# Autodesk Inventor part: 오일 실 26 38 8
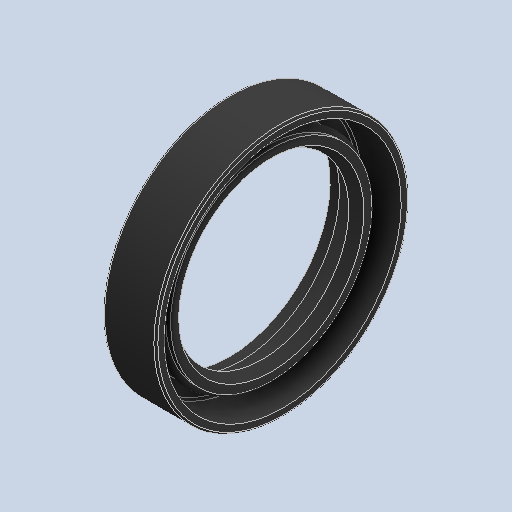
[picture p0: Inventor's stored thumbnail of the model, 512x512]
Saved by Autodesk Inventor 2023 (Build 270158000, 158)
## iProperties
Created: 2025-03
Part Number: 오일 실 26 38 8
Material: 고무
Description: 오일-실
Document SubType Name: Modeling
Designer: User
Density: 0.93 g/cm^3
Appearance: 기본값
Author: jhkim
Sending System: Autodesk Inventor 2025
Preprocessor: ST-DEVELOPER v20
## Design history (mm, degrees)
feature "Solid1"
node "솔리드1"
